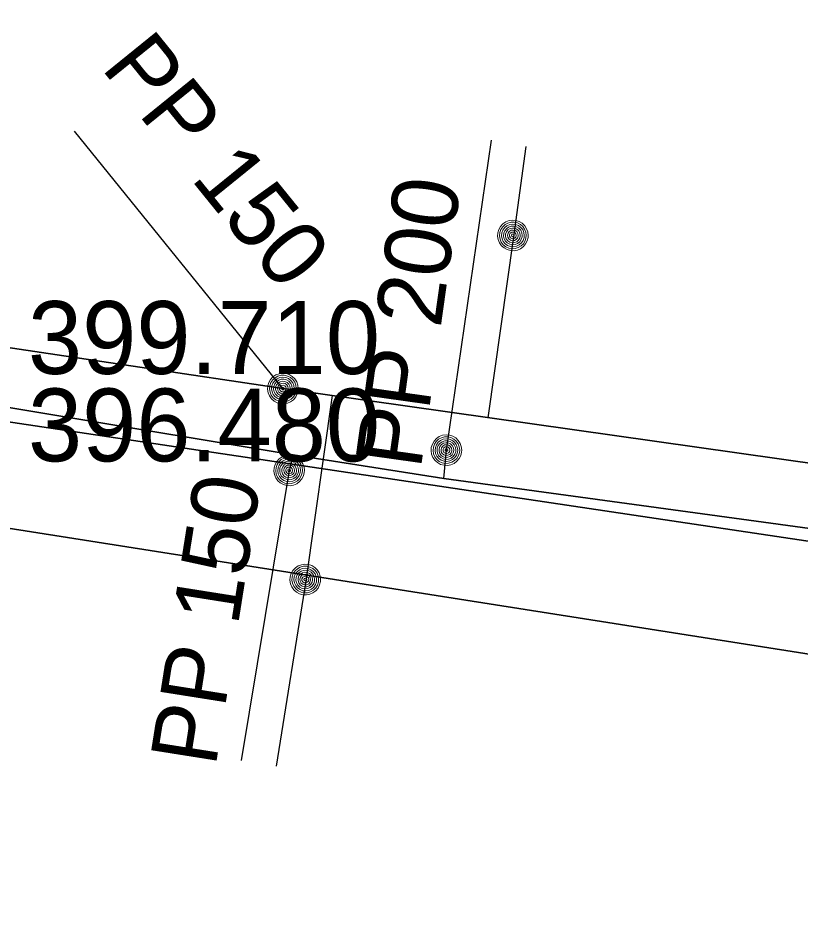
# Model space of a CAD drawing. Extents: x -866761 to -866592, y -1013996 to -1013877.
# Drawn here: x -866651.46 to -866639.65, y -1013979.36 to -1013965.9 of the extents above; entities that cross this region are included whole.
import ezdxf

# ---------------------------------------------------------------- set-up
doc = ezdxf.new("R2010")
doc.units = 0
doc.header["$LTSCALE"] = 0.44
for name, color, linetype, lineweight in [('1', 7, 'Continuous', 35), ('12', 7, 'Continuous', 13), ('21', 7, 'Continuous', 35), ('23', 7, 'Continuous', 25), ('25', 7, 'Continuous', 13), ('3', 7, 'Continuous', 25), ('32', 7, 'Continuous', 13)]:
    doc.layers.add(name, color=color, linetype=linetype, lineweight=lineweight)

msp = doc.modelspace()

# ---------------------------------------------------------------- linework, layer by layer
at = {"layer": '1'}
msp.add_line((-866612.967, -1013977.763), (-866734.931, -1013959.586), dxfattribs=at)
for points in [[(-866612.815, -1013977.108), (-866621.035, -1013976.325), (-866621.378, -1013976.297), (-866626.243, -1013975.519), (-866632.94, -1013974.51), (-866645.03, -1013972.86), (-866647.305, -1013972.501), (-866654.48, -1013971.31), (-866668.882, -1013969.171), (-866678.229, -1013967.78), (-866685.446, -1013966.718), (-866689.8, -1013966.06), (-866697.865, -1013964.927), (-866723.097, -1013961.352), (-866726.923, -1013960.77), (-866727.214, -1013960.734), (-866737.38, -1013959.64), (-866746.09, -1013958.48), (-866747.84, -1013958.25), (-866748.13, -1013958.99), (-866750.15, -1013958.69)], [(-866613.338, -1013979.363), (-866624.951, -1013977.802), (-866715.256, -1013963.593), (-866735.102, -1013960.577)]]:
    msp.add_lwpolyline(points, dxfattribs=at)
at = {"layer": '12'}
for points in [[(-866644.759, -1013972.43), (-866644.765, -1013972.378), (-866644.782, -1013972.328), (-866644.811, -1013972.284), (-866644.848, -1013972.247), (-866644.893, -1013972.22), (-866644.943, -1013972.203), (-866644.996, -1013972.199), (-866645.048, -1013972.206), (-866645.097, -1013972.225), (-866645.14, -1013972.254), (-866645.176, -1013972.293), (-866645.202, -1013972.338), (-866645.218, -1013972.389), (-866645.221, -1013972.441), (-866645.213, -1013972.493), (-866645.193, -1013972.542), (-866645.162, -1013972.585), (-866645.123, -1013972.619), (-866645.077, -1013972.645), (-866645.026, -1013972.659), (-866644.973, -1013972.661), (-866644.922, -1013972.651), (-866644.874, -1013972.63), (-866644.831, -1013972.599), (-866644.797, -1013972.558), (-866644.773, -1013972.512), (-866644.761, -1013972.461)], [(-866644.789, -1013972.43), (-866644.795, -1013972.381), (-866644.812, -1013972.335), (-866644.84, -1013972.295), (-866644.877, -1013972.263), (-866644.921, -1013972.241), (-866644.969, -1013972.23), (-866645.018, -1013972.23), (-866645.065, -1013972.243), (-866645.108, -1013972.267), (-866645.144, -1013972.3), (-866645.171, -1013972.341), (-866645.187, -1013972.388), (-866645.191, -1013972.437), (-866645.184, -1013972.485), (-866645.165, -1013972.53), (-866645.135, -1013972.57), (-866645.097, -1013972.601), (-866645.053, -1013972.621), (-866645.005, -1013972.631), (-866644.956, -1013972.629), (-866644.909, -1013972.614), (-866644.866, -1013972.589), (-866644.831, -1013972.555), (-866644.806, -1013972.513), (-866644.792, -1013972.466)], [(-866644.819, -1013972.43), (-866644.825, -1013972.385), (-866644.842, -1013972.343), (-866644.87, -1013972.308), (-866644.906, -1013972.281), (-866644.948, -1013972.264), (-866644.993, -1013972.259), (-866645.038, -1013972.265), (-866645.079, -1013972.284), (-866645.114, -1013972.312), (-866645.141, -1013972.349), (-866645.157, -1013972.391), (-866645.161, -1013972.436), (-866645.154, -1013972.481), (-866645.135, -1013972.522), (-866645.106, -1013972.556), (-866645.069, -1013972.582), (-866645.026, -1013972.598), (-866644.981, -1013972.601), (-866644.936, -1013972.593), (-866644.896, -1013972.573), (-866644.862, -1013972.544), (-866644.836, -1013972.506), (-866644.822, -1013972.463)], [(-866644.849, -1013972.43), (-866644.853, -1013972.389), (-866644.872, -1013972.352), (-866644.899, -1013972.321), (-866644.934, -1013972.3), (-866644.974, -1013972.289), (-866645.015, -1013972.291), (-866645.054, -1013972.304), (-866645.088, -1013972.328), (-866645.113, -1013972.36), (-866645.128, -1013972.398), (-866645.13, -1013972.439), (-866645.123, -1013972.479), (-866645.103, -1013972.515), (-866645.074, -1013972.544), (-866645.037, -1013972.563), (-866644.997, -1013972.571), (-866644.956, -1013972.567), (-866644.918, -1013972.552), (-866644.886, -1013972.526), (-866644.863, -1013972.492), (-866644.85, -1013972.453)], [(-866644.879, -1013972.43), (-866644.884, -1013972.394), (-866644.902, -1013972.362), (-866644.928, -1013972.337), (-866644.962, -1013972.322), (-866644.998, -1013972.319), (-866645.032, -1013972.327), (-866645.064, -1013972.347), (-866645.087, -1013972.375), (-866645.1, -1013972.409), (-866645.1, -1013972.446), (-866645.089, -1013972.481), (-866645.068, -1013972.51), (-866645.038, -1013972.531), (-866645.003, -1013972.541), (-866644.966, -1013972.539), (-866644.932, -1013972.525), (-866644.905, -1013972.502), (-866644.886, -1013972.47), (-866644.879, -1013972.435)], [(-866644.909, -1013972.43), (-866644.914, -1013972.399), (-866644.931, -1013972.373), (-866644.956, -1013972.356), (-866644.987, -1013972.349), (-866645.018, -1013972.353), (-866645.045, -1013972.37), (-866645.063, -1013972.394), (-866645.071, -1013972.425), (-866645.067, -1013972.455), (-866645.052, -1013972.483), (-866645.027, -1013972.502), (-866644.998, -1013972.511), (-866644.967, -1013972.508), (-866644.939, -1013972.494), (-866644.919, -1013972.47), (-866644.909, -1013972.441)], [(-866644.939, -1013972.43), (-866644.944, -1013972.406), (-866644.961, -1013972.388), (-866644.983, -1013972.379), (-866645.008, -1013972.382), (-866645.029, -1013972.396), (-866645.04, -1013972.418), (-866645.04, -1013972.443), (-866645.027, -1013972.464), (-866645.008, -1013972.478), (-866644.983, -1013972.481), (-866644.96, -1013972.472), (-866644.944, -1013972.454)], [(-866647.134, -1013972.737), (-866647.14, -1013972.685), (-866647.157, -1013972.635), (-866647.186, -1013972.591), (-866647.223, -1013972.554), (-866647.268, -1013972.527), (-866647.318, -1013972.51), (-866647.371, -1013972.506), (-866647.423, -1013972.513), (-866647.472, -1013972.532), (-866647.515, -1013972.561), (-866647.551, -1013972.6), (-866647.577, -1013972.645), (-866647.593, -1013972.696), (-866647.596, -1013972.748), (-866647.588, -1013972.8), (-866647.568, -1013972.849), (-866647.537, -1013972.892), (-866647.498, -1013972.926), (-866647.452, -1013972.952), (-866647.401, -1013972.966), (-866647.348, -1013972.968), (-866647.297, -1013972.958), (-866647.249, -1013972.937), (-866647.206, -1013972.906), (-866647.172, -1013972.865), (-866647.148, -1013972.819), (-866647.136, -1013972.768)], [(-866647.164, -1013972.737), (-866647.17, -1013972.688), (-866647.187, -1013972.642), (-866647.215, -1013972.602), (-866647.252, -1013972.57), (-866647.296, -1013972.548), (-866647.344, -1013972.537), (-866647.393, -1013972.537), (-866647.44, -1013972.55), (-866647.483, -1013972.574), (-866647.519, -1013972.607), (-866647.546, -1013972.648), (-866647.562, -1013972.695), (-866647.566, -1013972.744), (-866647.559, -1013972.792), (-866647.54, -1013972.837), (-866647.51, -1013972.877), (-866647.472, -1013972.908), (-866647.428, -1013972.928), (-866647.38, -1013972.938), (-866647.331, -1013972.936), (-866647.284, -1013972.921), (-866647.241, -1013972.896), (-866647.206, -1013972.862), (-866647.181, -1013972.82), (-866647.167, -1013972.773)], [(-866644.969, -1013972.43), (-866644.974, -1013972.415), (-866644.989, -1013972.409), (-866645.004, -1013972.413), (-866645.011, -1013972.427), (-866645.007, -1013972.442), (-866644.994, -1013972.451), (-866644.978, -1013972.448), (-866644.969, -1013972.436)], [(-866647.194, -1013972.737), (-866647.2, -1013972.692), (-866647.217, -1013972.65), (-866647.245, -1013972.615), (-866647.281, -1013972.588), (-866647.323, -1013972.571), (-866647.368, -1013972.566), (-866647.413, -1013972.572), (-866647.454, -1013972.591), (-866647.489, -1013972.619), (-866647.516, -1013972.656), (-866647.532, -1013972.698), (-866647.536, -1013972.743), (-866647.529, -1013972.788), (-866647.51, -1013972.829), (-866647.481, -1013972.863), (-866647.444, -1013972.889), (-866647.401, -1013972.905), (-866647.356, -1013972.908), (-866647.311, -1013972.9), (-866647.271, -1013972.88), (-866647.237, -1013972.851), (-866647.211, -1013972.813), (-866647.197, -1013972.77)], [(-866647.224, -1013972.737), (-866647.228, -1013972.696), (-866647.247, -1013972.659), (-866647.274, -1013972.628), (-866647.309, -1013972.607), (-866647.349, -1013972.596), (-866647.39, -1013972.598), (-866647.429, -1013972.611), (-866647.463, -1013972.635), (-866647.488, -1013972.667), (-866647.503, -1013972.705), (-866647.505, -1013972.746), (-866647.498, -1013972.786), (-866647.478, -1013972.822), (-866647.449, -1013972.851), (-866647.412, -1013972.87), (-866647.372, -1013972.878), (-866647.331, -1013972.874), (-866647.293, -1013972.859), (-866647.261, -1013972.833), (-866647.238, -1013972.799), (-866647.225, -1013972.76)], [(-866647.254, -1013972.737), (-866647.259, -1013972.701), (-866647.277, -1013972.669), (-866647.303, -1013972.644), (-866647.337, -1013972.629), (-866647.373, -1013972.626), (-866647.407, -1013972.634), (-866647.439, -1013972.654), (-866647.462, -1013972.682), (-866647.475, -1013972.716), (-866647.475, -1013972.753), (-866647.464, -1013972.788), (-866647.443, -1013972.817), (-866647.413, -1013972.838), (-866647.378, -1013972.848), (-866647.341, -1013972.846), (-866647.307, -1013972.832), (-866647.28, -1013972.809), (-866647.261, -1013972.777), (-866647.254, -1013972.742)], [(-866647.284, -1013972.737), (-866647.289, -1013972.706), (-866647.306, -1013972.68), (-866647.331, -1013972.663), (-866647.362, -1013972.656), (-866647.393, -1013972.66), (-866647.42, -1013972.677), (-866647.438, -1013972.701), (-866647.446, -1013972.732), (-866647.442, -1013972.762), (-866647.427, -1013972.79), (-866647.402, -1013972.809), (-866647.373, -1013972.818), (-866647.342, -1013972.815), (-866647.314, -1013972.801), (-866647.294, -1013972.777), (-866647.284, -1013972.748)], [(-866647.314, -1013972.737), (-866647.319, -1013972.713), (-866647.336, -1013972.695), (-866647.358, -1013972.686), (-866647.383, -1013972.689), (-866647.404, -1013972.703), (-866647.415, -1013972.725), (-866647.415, -1013972.75), (-866647.402, -1013972.771), (-866647.383, -1013972.785), (-866647.358, -1013972.788), (-866647.335, -1013972.779), (-866647.319, -1013972.761)], [(-866647.344, -1013972.737), (-866647.349, -1013972.722), (-866647.364, -1013972.716), (-866647.379, -1013972.72), (-866647.386, -1013972.734), (-866647.382, -1013972.749), (-866647.369, -1013972.758), (-866647.353, -1013972.755), (-866647.344, -1013972.743)]]:
    msp.add_lwpolyline(points, close=True, dxfattribs=at)
at = {"layer": '21'}
for p, q in [((-866709.04, -1013962.31), (-866647.459, -1013971.5)), ((-866647.459, -1013971.5), (-866622.959, -1013974.98))]:
    msp.add_line(p, q, dxfattribs=at)
at = {"layer": '23'}
msp.add_line((-866647.459, -1013971.5), (-866650.605, -1013967.613), dxfattribs=at)
for points in [[(-866644.358, -1013971.941), (-866643.97, -1013969.21), (-866643.784, -1013967.843)], [(-866646.713, -1013971.606), (-866647.111, -1013974.405), (-866647.563, -1013977.204)]]:
    msp.add_lwpolyline(points, dxfattribs=at)
at = {"layer": '3'}
for points in [[(-866645.03, -1013972.86), (-866644.99, -1013972.43), (-866644.31, -1013967.75)], [(-866647.305, -1013972.501), (-866647.365, -1013972.737), (-866648.09, -1013977.12)]]:
    msp.add_lwpolyline(points, dxfattribs=at)
at = {"layer": '32'}
for points in [[(-866643.755, -1013969.188), (-866643.761, -1013969.136), (-866643.778, -1013969.086), (-866643.807, -1013969.042), (-866643.844, -1013969.005), (-866643.889, -1013968.978), (-866643.939, -1013968.961), (-866643.992, -1013968.957), (-866644.044, -1013968.964), (-866644.093, -1013968.983), (-866644.136, -1013969.012), (-866644.172, -1013969.051), (-866644.198, -1013969.096), (-866644.214, -1013969.147), (-866644.217, -1013969.199), (-866644.209, -1013969.251), (-866644.189, -1013969.3), (-866644.158, -1013969.343), (-866644.119, -1013969.377), (-866644.073, -1013969.403), (-866644.022, -1013969.417), (-866643.969, -1013969.419), (-866643.918, -1013969.409), (-866643.87, -1013969.388), (-866643.827, -1013969.357), (-866643.793, -1013969.316), (-866643.769, -1013969.27), (-866643.757, -1013969.219)], [(-866643.785, -1013969.188), (-866643.791, -1013969.139), (-866643.808, -1013969.093), (-866643.836, -1013969.053), (-866643.873, -1013969.021), (-866643.917, -1013968.999), (-866643.965, -1013968.988), (-866644.014, -1013968.988), (-866644.061, -1013969.001), (-866644.104, -1013969.025), (-866644.14, -1013969.058), (-866644.167, -1013969.099), (-866644.183, -1013969.146), (-866644.187, -1013969.195), (-866644.18, -1013969.243), (-866644.161, -1013969.288), (-866644.131, -1013969.328), (-866644.093, -1013969.359), (-866644.049, -1013969.379), (-866644.001, -1013969.389), (-866643.952, -1013969.387), (-866643.905, -1013969.372), (-866643.862, -1013969.347), (-866643.828, -1013969.313), (-866643.802, -1013969.271), (-866643.788, -1013969.224)], [(-866643.815, -1013969.188), (-866643.821, -1013969.143), (-866643.838, -1013969.101), (-866643.866, -1013969.066), (-866643.902, -1013969.039), (-866643.944, -1013969.022), (-866643.989, -1013969.017), (-866644.034, -1013969.023), (-866644.075, -1013969.042), (-866644.11, -1013969.07), (-866644.137, -1013969.107), (-866644.153, -1013969.149), (-866644.157, -1013969.194), (-866644.15, -1013969.239), (-866644.131, -1013969.28), (-866644.102, -1013969.314), (-866644.065, -1013969.34), (-866644.022, -1013969.356), (-866643.977, -1013969.359), (-866643.932, -1013969.351), (-866643.892, -1013969.331), (-866643.858, -1013969.302), (-866643.832, -1013969.264), (-866643.818, -1013969.221)], [(-866643.845, -1013969.188), (-866643.85, -1013969.147), (-866643.868, -1013969.11), (-866643.895, -1013969.079), (-866643.93, -1013969.058), (-866643.97, -1013969.047), (-866644.011, -1013969.049), (-866644.05, -1013969.062), (-866644.084, -1013969.086), (-866644.109, -1013969.118), (-866644.124, -1013969.156), (-866644.127, -1013969.197), (-866644.119, -1013969.237), (-866644.099, -1013969.273), (-866644.07, -1013969.302), (-866644.033, -1013969.321), (-866643.993, -1013969.329), (-866643.952, -1013969.325), (-866643.914, -1013969.31), (-866643.882, -1013969.284), (-866643.859, -1013969.25), (-866643.846, -1013969.211)], [(-866643.875, -1013969.188), (-866643.88, -1013969.152), (-866643.898, -1013969.12), (-866643.924, -1013969.095), (-866643.958, -1013969.08), (-866643.994, -1013969.077), (-866644.029, -1013969.085), (-866644.06, -1013969.105), (-866644.083, -1013969.133), (-866644.096, -1013969.167), (-866644.096, -1013969.204), (-866644.085, -1013969.239), (-866644.064, -1013969.268), (-866644.034, -1013969.289), (-866643.999, -1013969.299), (-866643.962, -1013969.297), (-866643.928, -1013969.283), (-866643.901, -1013969.26), (-866643.882, -1013969.228), (-866643.875, -1013969.193)], [(-866643.905, -1013969.188), (-866643.91, -1013969.157), (-866643.927, -1013969.131), (-866643.953, -1013969.114), (-866643.983, -1013969.107), (-866644.014, -1013969.111), (-866644.041, -1013969.128), (-866644.059, -1013969.152), (-866644.067, -1013969.183), (-866644.063, -1013969.213), (-866644.048, -1013969.241), (-866644.024, -1013969.26), (-866643.994, -1013969.269), (-866643.963, -1013969.266), (-866643.935, -1013969.252), (-866643.915, -1013969.228), (-866643.905, -1013969.199)], [(-866643.935, -1013969.188), (-866643.94, -1013969.164), (-866643.957, -1013969.146), (-866643.98, -1013969.137), (-866644.004, -1013969.14), (-866644.025, -1013969.154), (-866644.036, -1013969.176), (-866644.036, -1013969.201), (-866644.024, -1013969.222), (-866644.004, -1013969.236), (-866643.979, -1013969.239), (-866643.956, -1013969.23), (-866643.94, -1013969.212)], [(-866643.965, -1013969.188), (-866643.97, -1013969.173), (-866643.985, -1013969.167), (-866644, -1013969.171), (-866644.007, -1013969.185), (-866644.003, -1013969.2), (-866643.99, -1013969.209), (-866643.975, -1013969.206), (-866643.965, -1013969.194)], [(-866647.228, -1013971.5), (-866647.234, -1013971.448), (-866647.251, -1013971.398), (-866647.28, -1013971.354), (-866647.317, -1013971.317), (-866647.362, -1013971.29), (-866647.412, -1013971.273), (-866647.465, -1013971.269), (-866647.517, -1013971.276), (-866647.566, -1013971.295), (-866647.609, -1013971.324), (-866647.645, -1013971.363), (-866647.671, -1013971.408), (-866647.687, -1013971.459), (-866647.69, -1013971.511), (-866647.682, -1013971.563), (-866647.662, -1013971.612), (-866647.631, -1013971.655), (-866647.592, -1013971.689), (-866647.546, -1013971.715), (-866647.495, -1013971.729), (-866647.442, -1013971.731), (-866647.391, -1013971.721), (-866647.343, -1013971.7), (-866647.3, -1013971.669), (-866647.266, -1013971.628), (-866647.242, -1013971.582), (-866647.23, -1013971.531)], [(-866647.258, -1013971.5), (-866647.264, -1013971.451), (-866647.281, -1013971.405), (-866647.309, -1013971.365), (-866647.346, -1013971.333), (-866647.39, -1013971.311), (-866647.438, -1013971.3), (-866647.487, -1013971.3), (-866647.534, -1013971.313), (-866647.577, -1013971.337), (-866647.613, -1013971.37), (-866647.64, -1013971.411), (-866647.656, -1013971.458), (-866647.66, -1013971.507), (-866647.653, -1013971.555), (-866647.634, -1013971.6), (-866647.604, -1013971.64), (-866647.566, -1013971.671), (-866647.522, -1013971.691), (-866647.474, -1013971.701), (-866647.425, -1013971.699), (-866647.378, -1013971.684), (-866647.335, -1013971.659), (-866647.301, -1013971.625), (-866647.275, -1013971.583), (-866647.261, -1013971.536)], [(-866647.288, -1013971.5), (-866647.294, -1013971.455), (-866647.311, -1013971.413), (-866647.339, -1013971.378), (-866647.375, -1013971.351), (-866647.417, -1013971.334), (-866647.462, -1013971.329), (-866647.507, -1013971.335), (-866647.548, -1013971.354), (-866647.583, -1013971.382), (-866647.61, -1013971.419), (-866647.626, -1013971.461), (-866647.63, -1013971.506), (-866647.623, -1013971.551), (-866647.604, -1013971.592), (-866647.575, -1013971.626), (-866647.538, -1013971.652), (-866647.495, -1013971.668), (-866647.45, -1013971.671), (-866647.405, -1013971.663), (-866647.365, -1013971.643), (-866647.331, -1013971.614), (-866647.305, -1013971.576), (-866647.291, -1013971.533)], [(-866647.318, -1013971.5), (-866647.323, -1013971.459), (-866647.341, -1013971.422), (-866647.368, -1013971.391), (-866647.403, -1013971.37), (-866647.443, -1013971.359), (-866647.484, -1013971.361), (-866647.523, -1013971.374), (-866647.557, -1013971.398), (-866647.582, -1013971.43), (-866647.597, -1013971.468), (-866647.6, -1013971.509), (-866647.592, -1013971.549), (-866647.572, -1013971.585), (-866647.543, -1013971.614), (-866647.506, -1013971.633), (-866647.466, -1013971.641), (-866647.425, -1013971.637), (-866647.387, -1013971.622), (-866647.355, -1013971.596), (-866647.332, -1013971.562), (-866647.319, -1013971.523)], [(-866647.348, -1013971.5), (-866647.353, -1013971.464), (-866647.371, -1013971.432), (-866647.397, -1013971.407), (-866647.431, -1013971.392), (-866647.467, -1013971.389), (-866647.502, -1013971.397), (-866647.533, -1013971.417), (-866647.556, -1013971.445), (-866647.569, -1013971.479), (-866647.569, -1013971.516), (-866647.558, -1013971.551), (-866647.537, -1013971.58), (-866647.507, -1013971.601), (-866647.472, -1013971.611), (-866647.435, -1013971.609), (-866647.401, -1013971.595), (-866647.374, -1013971.572), (-866647.355, -1013971.54), (-866647.348, -1013971.505)], [(-866647.378, -1013971.5), (-866647.383, -1013971.469), (-866647.4, -1013971.443), (-866647.426, -1013971.426), (-866647.456, -1013971.419), (-866647.487, -1013971.423), (-866647.514, -1013971.44), (-866647.532, -1013971.464), (-866647.54, -1013971.495), (-866647.536, -1013971.525), (-866647.521, -1013971.553), (-866647.497, -1013971.572), (-866647.467, -1013971.581), (-866647.436, -1013971.578), (-866647.408, -1013971.564), (-866647.388, -1013971.54), (-866647.378, -1013971.511)], [(-866647.408, -1013971.5), (-866647.413, -1013971.476), (-866647.43, -1013971.458), (-866647.453, -1013971.449), (-866647.477, -1013971.452), (-866647.498, -1013971.466), (-866647.509, -1013971.488), (-866647.509, -1013971.513), (-866647.497, -1013971.534), (-866647.477, -1013971.548), (-866647.452, -1013971.551), (-866647.429, -1013971.542), (-866647.413, -1013971.524)], [(-866647.438, -1013971.5), (-866647.443, -1013971.485), (-866647.458, -1013971.479), (-866647.473, -1013971.483), (-866647.48, -1013971.497), (-866647.476, -1013971.512), (-866647.463, -1013971.521), (-866647.448, -1013971.518), (-866647.438, -1013971.506)], [(-866646.89, -1013974.385), (-866646.896, -1013974.333), (-866646.913, -1013974.283), (-866646.942, -1013974.239), (-866646.979, -1013974.202), (-866647.024, -1013974.175), (-866647.074, -1013974.158), (-866647.127, -1013974.154), (-866647.179, -1013974.161), (-866647.228, -1013974.18), (-866647.271, -1013974.209), (-866647.307, -1013974.248), (-866647.333, -1013974.293), (-866647.349, -1013974.344), (-866647.352, -1013974.396), (-866647.344, -1013974.448), (-866647.324, -1013974.497), (-866647.293, -1013974.54), (-866647.254, -1013974.574), (-866647.208, -1013974.6), (-866647.157, -1013974.614), (-866647.104, -1013974.616), (-866647.053, -1013974.606), (-866647.005, -1013974.585), (-866646.962, -1013974.554), (-866646.928, -1013974.513), (-866646.904, -1013974.467), (-866646.892, -1013974.416)], [(-866646.92, -1013974.385), (-866646.926, -1013974.336), (-866646.943, -1013974.29), (-866646.971, -1013974.25), (-866647.008, -1013974.218), (-866647.052, -1013974.196), (-866647.1, -1013974.185), (-866647.149, -1013974.185), (-866647.196, -1013974.198), (-866647.239, -1013974.222), (-866647.275, -1013974.255), (-866647.302, -1013974.296), (-866647.318, -1013974.343), (-866647.322, -1013974.392), (-866647.315, -1013974.44), (-866647.296, -1013974.485), (-866647.266, -1013974.525), (-866647.228, -1013974.556), (-866647.184, -1013974.576), (-866647.136, -1013974.586), (-866647.087, -1013974.584), (-866647.04, -1013974.569), (-866646.997, -1013974.544), (-866646.963, -1013974.51), (-866646.937, -1013974.468), (-866646.923, -1013974.421)], [(-866646.95, -1013974.385), (-866646.956, -1013974.34), (-866646.973, -1013974.298), (-866647.001, -1013974.263), (-866647.037, -1013974.236), (-866647.079, -1013974.219), (-866647.124, -1013974.214), (-866647.169, -1013974.22), (-866647.21, -1013974.239), (-866647.245, -1013974.267), (-866647.272, -1013974.304), (-866647.288, -1013974.346), (-866647.292, -1013974.391), (-866647.285, -1013974.436), (-866647.266, -1013974.477), (-866647.237, -1013974.511), (-866647.2, -1013974.537), (-866647.157, -1013974.553), (-866647.112, -1013974.556), (-866647.067, -1013974.548), (-866647.027, -1013974.528), (-866646.993, -1013974.499), (-866646.967, -1013974.461), (-866646.953, -1013974.418)], [(-866646.98, -1013974.385), (-866646.985, -1013974.344), (-866647.003, -1013974.307), (-866647.03, -1013974.276), (-866647.065, -1013974.255), (-866647.105, -1013974.244), (-866647.146, -1013974.246), (-866647.185, -1013974.259), (-866647.219, -1013974.283), (-866647.244, -1013974.315), (-866647.259, -1013974.353), (-866647.262, -1013974.394), (-866647.254, -1013974.434), (-866647.234, -1013974.47), (-866647.205, -1013974.499), (-866647.168, -1013974.518), (-866647.128, -1013974.526), (-866647.087, -1013974.522), (-866647.049, -1013974.507), (-866647.017, -1013974.481), (-866646.994, -1013974.447), (-866646.981, -1013974.408)], [(-866647.01, -1013974.385), (-866647.015, -1013974.349), (-866647.033, -1013974.317), (-866647.059, -1013974.292), (-866647.093, -1013974.277), (-866647.129, -1013974.274), (-866647.164, -1013974.282), (-866647.195, -1013974.302), (-866647.218, -1013974.33), (-866647.231, -1013974.364), (-866647.231, -1013974.401), (-866647.22, -1013974.436), (-866647.199, -1013974.465), (-866647.169, -1013974.486), (-866647.134, -1013974.496), (-866647.097, -1013974.494), (-866647.063, -1013974.48), (-866647.036, -1013974.457), (-866647.017, -1013974.425), (-866647.01, -1013974.39)], [(-866647.04, -1013974.385), (-866647.045, -1013974.354), (-866647.062, -1013974.328), (-866647.088, -1013974.311), (-866647.118, -1013974.304), (-866647.149, -1013974.308), (-866647.176, -1013974.325), (-866647.194, -1013974.349), (-866647.202, -1013974.38), (-866647.198, -1013974.41), (-866647.183, -1013974.438), (-866647.159, -1013974.457), (-866647.129, -1013974.466), (-866647.098, -1013974.463), (-866647.07, -1013974.449), (-866647.05, -1013974.425), (-866647.04, -1013974.396)], [(-866647.07, -1013974.385), (-866647.075, -1013974.361), (-866647.092, -1013974.343), (-866647.115, -1013974.334), (-866647.139, -1013974.337), (-866647.16, -1013974.351), (-866647.171, -1013974.373), (-866647.171, -1013974.398), (-866647.159, -1013974.419), (-866647.139, -1013974.433), (-866647.114, -1013974.436), (-866647.091, -1013974.427), (-866647.075, -1013974.409)], [(-866647.1, -1013974.385), (-866647.105, -1013974.37), (-866647.12, -1013974.364), (-866647.135, -1013974.368), (-866647.142, -1013974.382), (-866647.138, -1013974.397), (-866647.125, -1013974.406), (-866647.11, -1013974.403), (-866647.1, -1013974.391)]]:
    msp.add_lwpolyline(points, close=True, dxfattribs=at)

# ---------------------------------------------------------------- texts
at = {"layer": '23'}
for s, rotation, p in [('PP 150', 309, (-866650.219, -1013966.657)), ('PP 200', 82, (-866645.379, -1013972.735)), ('PP 150', 81, (-866648.477, -1013977.227))]:
    msp.add_text(s, height=1, rotation=rotation, dxfattribs=at).set_placement(p)
at = {"layer": '25'}
for s, p in [('399.710 ', (-866651.309, -1013971.28)), ('396.480 ', (-866651.309, -1013972.6))]:
    msp.add_text(s, height=1.1, dxfattribs=at).set_placement(p)

doc.saveas('drawing.dxf')
